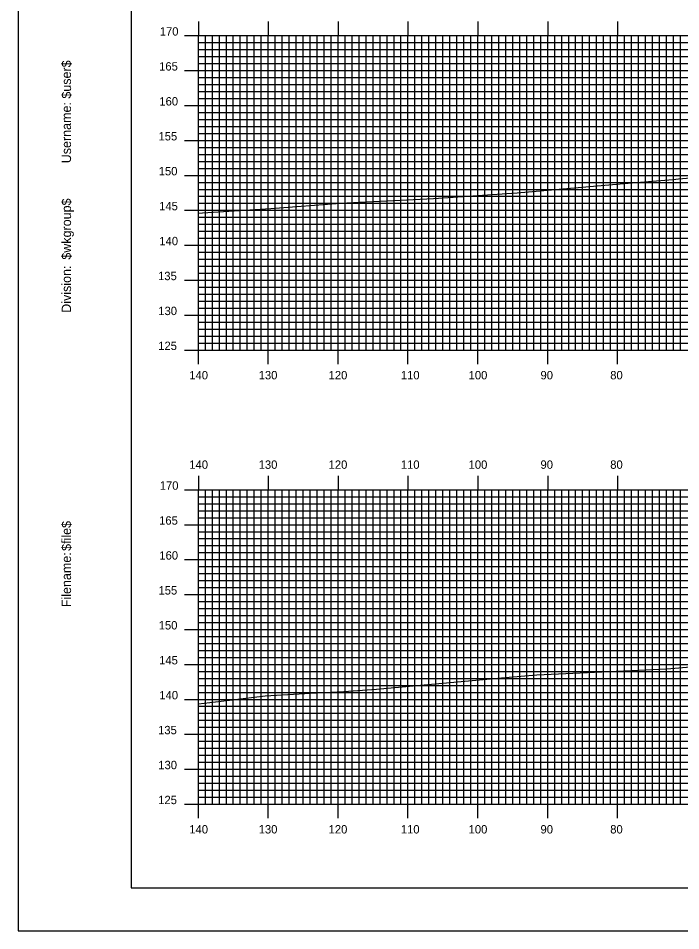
# Model space of a CAD drawing. Extents: x 1783041 to 1783384, y 442591 to 442811.
# Drawn here: x 1783040.7 to 1783135.5, y 442590.5 to 442721.2 of the extents above; entities that cross this region are included whole.
import ezdxf

# ---------------------------------------------------------------- set-up
doc = ezdxf.new("R2010")
doc.units = 0
for name, color, linetype in [('BORDER', 7, 'Continuous'), ('H_V ANNOTATION', 7, 'Continuous'), ('MAJOR', 7, 'Continuous'), ('MINOR', 7, 'Continuous'), ('PLOT BOUNDARY', 7, 'Continuous'), ('S_Roadway_Centerline', 7, 'Continuous')]:
    doc.layers.add(name, color=color, linetype=linetype)

msp = doc.modelspace()

# ---------------------------------------------------------------- linework, layer by layer
at = {"layer": 'BORDER'}
msp.add_lwpolyline([(1783056.86, 442596.67), (1783376.86, 442596.67), (1783376.86, 442806.67), (1783056.86, 442806.67)], close=True, dxfattribs=at)
at = {"layer": 'MAJOR'}
for p, q in [((1783066.46, 442720.67), (1783066.46, 442718.67)), ((1783076.46, 442720.67), (1783076.46, 442718.67)), ((1783086.46, 442720.67), (1783086.46, 442718.67)), ((1783096.46, 442720.67), (1783096.46, 442718.67)), ((1783106.46, 442720.67), (1783106.46, 442718.67)), ((1783116.46, 442720.67), (1783116.46, 442718.67)), ((1783126.46, 442720.67), (1783126.46, 442718.67)), ((1783064.46, 442718.67), (1783066.46, 442718.67)), ((1783066.46, 442718.67), (1783346.46, 442718.67)), ((1783066.46, 442673.67), (1783066.46, 442718.67)), ((1783066.46, 442673.67), (1783066.46, 442718.67)), ((1783066.46, 442718.67), (1783346.46, 442718.67)), ((1783076.46, 442673.67), (1783076.46, 442718.67)), ((1783086.46, 442673.67), (1783086.46, 442718.67)), ((1783096.46, 442673.67), (1783096.46, 442718.67)), ((1783106.46, 442673.67), (1783106.46, 442718.67)), ((1783116.46, 442673.67), (1783116.46, 442718.67)), ((1783126.46, 442673.67), (1783126.46, 442718.67)), ((1783064.46, 442713.67), (1783066.46, 442713.67)), ((1783066.46, 442713.67), (1783346.46, 442713.67)), ((1783064.46, 442708.67), (1783066.46, 442708.67)), ((1783066.46, 442708.67), (1783346.46, 442708.67)), ((1783064.46, 442703.67), (1783066.46, 442703.67)), ((1783066.46, 442703.67), (1783346.46, 442703.67)), ((1783064.46, 442698.67), (1783066.46, 442698.67)), ((1783066.46, 442698.67), (1783346.46, 442698.67)), ((1783064.46, 442693.67), (1783066.46, 442693.67)), ((1783066.46, 442693.67), (1783346.46, 442693.67)), ((1783064.46, 442688.67), (1783066.46, 442688.67)), ((1783066.46, 442688.67), (1783346.46, 442688.67)), ((1783064.46, 442683.67), (1783066.46, 442683.67)), ((1783066.46, 442683.67), (1783346.46, 442683.67)), ((1783064.46, 442678.67), (1783066.46, 442678.67)), ((1783066.46, 442678.67), (1783346.46, 442678.67)), ((1783064.46, 442673.67), (1783066.46, 442673.67)), ((1783066.46, 442673.67), (1783346.46, 442673.67)), ((1783066.46, 442673.67), (1783346.46, 442673.67)), ((1783066.46, 442671.66), (1783066.46, 442673.67)), ((1783076.46, 442671.66), (1783076.46, 442673.67)), ((1783086.46, 442671.66), (1783086.46, 442673.67)), ((1783096.46, 442671.66), (1783096.46, 442673.67)), ((1783106.46, 442671.66), (1783106.46, 442673.67)), ((1783116.46, 442671.66), (1783116.46, 442673.67)), ((1783126.46, 442671.66), (1783126.46, 442673.67)), ((1783066.46, 442655.67), (1783066.46, 442653.67)), ((1783076.46, 442655.67), (1783076.46, 442653.67)), ((1783086.46, 442655.67), (1783086.46, 442653.67)), ((1783096.46, 442655.67), (1783096.46, 442653.67)), ((1783106.46, 442655.67), (1783106.46, 442653.67)), ((1783116.46, 442655.67), (1783116.46, 442653.67)), ((1783126.46, 442655.67), (1783126.46, 442653.67)), ((1783064.46, 442653.67), (1783066.46, 442653.67)), ((1783066.46, 442653.67), (1783346.46, 442653.67)), ((1783066.46, 442608.67), (1783066.46, 442653.67)), ((1783066.46, 442608.67), (1783066.46, 442653.67)), ((1783066.46, 442653.67), (1783346.46, 442653.67)), ((1783076.46, 442608.67), (1783076.46, 442653.67)), ((1783086.46, 442608.67), (1783086.46, 442653.67)), ((1783096.46, 442608.67), (1783096.46, 442653.67)), ((1783106.46, 442608.67), (1783106.46, 442653.67)), ((1783116.46, 442608.67), (1783116.46, 442653.67)), ((1783126.46, 442608.67), (1783126.46, 442653.67)), ((1783064.46, 442648.67), (1783066.46, 442648.67)), ((1783066.46, 442648.67), (1783346.46, 442648.67)), ((1783064.46, 442643.67), (1783066.46, 442643.67)), ((1783066.46, 442643.67), (1783346.46, 442643.67)), ((1783064.46, 442638.67), (1783066.46, 442638.67)), ((1783066.46, 442638.67), (1783346.46, 442638.67)), ((1783064.46, 442633.67), (1783066.46, 442633.67)), ((1783066.46, 442633.67), (1783346.46, 442633.67)), ((1783064.46, 442628.67), (1783066.46, 442628.67)), ((1783066.46, 442628.67), (1783346.46, 442628.67)), ((1783064.46, 442623.67), (1783066.46, 442623.67)), ((1783066.46, 442623.67), (1783346.46, 442623.67)), ((1783064.46, 442618.67), (1783066.46, 442618.67)), ((1783066.46, 442618.67), (1783346.46, 442618.67)), ((1783064.46, 442613.67), (1783066.46, 442613.67)), ((1783066.46, 442613.67), (1783346.46, 442613.67)), ((1783064.46, 442608.67), (1783066.46, 442608.67)), ((1783066.46, 442608.67), (1783346.46, 442608.67)), ((1783066.46, 442608.67), (1783346.46, 442608.67)), ((1783066.46, 442606.66), (1783066.46, 442608.67)), ((1783076.46, 442606.66), (1783076.46, 442608.67)), ((1783086.46, 442606.66), (1783086.46, 442608.67)), ((1783096.46, 442606.66), (1783096.46, 442608.67)), ((1783106.46, 442606.66), (1783106.46, 442608.67)), ((1783116.46, 442606.66), (1783116.46, 442608.67)), ((1783126.46, 442606.66), (1783126.46, 442608.67))]:
    msp.add_line(p, q, dxfattribs=at)
at = {"layer": 'MINOR'}
for p, q in [((1783067.46, 442673.67), (1783067.46, 442718.67)), ((1783068.46, 442673.67), (1783068.46, 442718.67)), ((1783069.46, 442673.67), (1783069.46, 442718.67)), ((1783070.46, 442673.67), (1783070.46, 442718.67)), ((1783071.46, 442673.67), (1783071.46, 442718.67)), ((1783072.46, 442673.67), (1783072.46, 442718.67)), ((1783073.46, 442673.67), (1783073.46, 442718.67)), ((1783074.46, 442673.67), (1783074.46, 442718.67)), ((1783075.46, 442673.67), (1783075.46, 442718.67)), ((1783077.46, 442673.67), (1783077.46, 442718.67)), ((1783078.46, 442673.67), (1783078.46, 442718.67)), ((1783079.46, 442673.67), (1783079.46, 442718.67)), ((1783080.46, 442673.67), (1783080.46, 442718.67)), ((1783081.46, 442673.67), (1783081.46, 442718.67)), ((1783082.46, 442673.67), (1783082.46, 442718.67)), ((1783083.46, 442673.67), (1783083.46, 442718.67)), ((1783084.46, 442673.67), (1783084.46, 442718.67)), ((1783085.46, 442673.67), (1783085.46, 442718.67)), ((1783087.46, 442673.67), (1783087.46, 442718.67)), ((1783088.46, 442673.67), (1783088.46, 442718.67)), ((1783089.46, 442673.67), (1783089.46, 442718.67)), ((1783090.46, 442673.67), (1783090.46, 442718.67)), ((1783091.46, 442673.67), (1783091.46, 442718.67)), ((1783092.46, 442673.67), (1783092.46, 442718.67)), ((1783093.46, 442673.67), (1783093.46, 442718.67)), ((1783094.46, 442673.67), (1783094.46, 442718.67)), ((1783095.46, 442673.67), (1783095.46, 442718.67)), ((1783097.46, 442673.67), (1783097.46, 442718.67)), ((1783098.46, 442673.67), (1783098.46, 442718.67)), ((1783099.46, 442673.67), (1783099.46, 442718.67)), ((1783100.46, 442673.67), (1783100.46, 442718.67)), ((1783101.46, 442673.67), (1783101.46, 442718.67)), ((1783102.46, 442673.67), (1783102.46, 442718.67)), ((1783103.46, 442673.67), (1783103.46, 442718.67)), ((1783104.46, 442673.67), (1783104.46, 442718.67)), ((1783105.46, 442673.67), (1783105.46, 442718.67)), ((1783107.46, 442673.67), (1783107.46, 442718.67)), ((1783108.46, 442673.67), (1783108.46, 442718.67)), ((1783109.46, 442673.67), (1783109.46, 442718.67)), ((1783110.46, 442673.67), (1783110.46, 442718.67)), ((1783111.46, 442673.67), (1783111.46, 442718.67)), ((1783112.46, 442673.67), (1783112.46, 442718.67)), ((1783113.46, 442673.67), (1783113.46, 442718.67)), ((1783114.46, 442673.67), (1783114.46, 442718.67)), ((1783115.46, 442673.67), (1783115.46, 442718.67)), ((1783117.46, 442673.67), (1783117.46, 442718.67)), ((1783118.46, 442673.67), (1783118.46, 442718.67)), ((1783119.46, 442673.67), (1783119.46, 442718.67)), ((1783120.46, 442673.67), (1783120.46, 442718.67)), ((1783121.46, 442673.67), (1783121.46, 442718.67)), ((1783122.46, 442673.67), (1783122.46, 442718.67)), ((1783123.46, 442673.67), (1783123.46, 442718.67)), ((1783124.46, 442673.67), (1783124.46, 442718.67)), ((1783125.46, 442673.67), (1783125.46, 442718.67)), ((1783127.46, 442673.67), (1783127.46, 442718.67)), ((1783128.46, 442673.67), (1783128.46, 442718.67)), ((1783129.46, 442673.67), (1783129.46, 442718.67)), ((1783130.46, 442673.67), (1783130.46, 442718.67)), ((1783131.46, 442673.67), (1783131.46, 442718.67)), ((1783132.46, 442673.67), (1783132.46, 442718.67)), ((1783133.46, 442673.67), (1783133.46, 442718.67)), ((1783134.46, 442673.67), (1783134.46, 442718.67)), ((1783135.46, 442673.67), (1783135.46, 442718.67)), ((1783066.46, 442717.67), (1783346.46, 442717.67)), ((1783066.46, 442717.67), (1783068.46, 442717.67)), ((1783066.46, 442716.67), (1783346.46, 442716.67)), ((1783066.46, 442716.67), (1783068.46, 442716.67)), ((1783066.46, 442715.67), (1783346.46, 442715.67)), ((1783066.46, 442715.67), (1783068.46, 442715.67)), ((1783066.46, 442714.67), (1783346.46, 442714.67)), ((1783066.46, 442714.67), (1783068.46, 442714.67)), ((1783066.46, 442712.67), (1783346.46, 442712.67)), ((1783066.46, 442712.67), (1783068.46, 442712.67)), ((1783066.46, 442711.67), (1783346.46, 442711.67)), ((1783066.46, 442711.67), (1783068.46, 442711.67)), ((1783066.46, 442710.67), (1783346.46, 442710.67)), ((1783066.46, 442710.67), (1783068.46, 442710.67)), ((1783066.46, 442709.67), (1783346.46, 442709.67)), ((1783066.46, 442709.67), (1783068.46, 442709.67)), ((1783066.46, 442707.67), (1783346.46, 442707.67)), ((1783066.46, 442707.67), (1783068.46, 442707.67)), ((1783066.46, 442706.67), (1783346.46, 442706.67)), ((1783066.46, 442706.67), (1783068.46, 442706.67)), ((1783066.46, 442705.67), (1783346.46, 442705.67)), ((1783066.46, 442705.67), (1783068.46, 442705.67)), ((1783066.46, 442704.67), (1783346.46, 442704.67)), ((1783066.46, 442704.67), (1783068.46, 442704.67)), ((1783066.46, 442702.67), (1783346.46, 442702.67)), ((1783066.46, 442702.67), (1783068.46, 442702.67)), ((1783066.46, 442701.67), (1783346.46, 442701.67)), ((1783066.46, 442701.67), (1783068.46, 442701.67)), ((1783066.46, 442700.67), (1783346.46, 442700.67)), ((1783066.46, 442700.67), (1783068.46, 442700.67)), ((1783066.46, 442699.67), (1783346.46, 442699.67)), ((1783066.46, 442699.67), (1783068.46, 442699.67)), ((1783066.46, 442697.67), (1783346.46, 442697.67)), ((1783066.46, 442697.67), (1783068.46, 442697.67)), ((1783066.46, 442696.67), (1783346.46, 442696.67)), ((1783066.46, 442696.67), (1783068.46, 442696.67)), ((1783066.46, 442695.67), (1783346.46, 442695.67)), ((1783066.46, 442695.67), (1783068.46, 442695.67)), ((1783066.46, 442694.67), (1783346.46, 442694.67)), ((1783066.46, 442694.67), (1783068.46, 442694.67)), ((1783066.46, 442692.67), (1783346.46, 442692.67)), ((1783066.46, 442692.67), (1783068.46, 442692.67)), ((1783066.46, 442691.67), (1783346.46, 442691.67)), ((1783066.46, 442691.67), (1783068.46, 442691.67)), ((1783066.46, 442690.67), (1783346.46, 442690.67)), ((1783066.46, 442690.67), (1783068.46, 442690.67)), ((1783066.46, 442689.67), (1783346.46, 442689.67)), ((1783066.46, 442689.67), (1783068.46, 442689.67)), ((1783066.46, 442687.67), (1783346.46, 442687.67)), ((1783066.46, 442687.67), (1783068.46, 442687.67)), ((1783066.46, 442686.67), (1783346.46, 442686.67)), ((1783066.46, 442686.67), (1783068.46, 442686.67)), ((1783066.46, 442685.67), (1783346.46, 442685.67)), ((1783066.46, 442685.67), (1783068.46, 442685.67)), ((1783066.46, 442684.67), (1783346.46, 442684.67)), ((1783066.46, 442684.67), (1783068.46, 442684.67)), ((1783066.46, 442682.67), (1783346.46, 442682.67)), ((1783066.46, 442682.67), (1783068.46, 442682.67)), ((1783066.46, 442681.67), (1783346.46, 442681.67)), ((1783066.46, 442681.67), (1783068.46, 442681.67)), ((1783066.46, 442680.67), (1783346.46, 442680.67)), ((1783066.46, 442680.67), (1783068.46, 442680.67)), ((1783066.46, 442679.67), (1783346.46, 442679.67)), ((1783066.46, 442679.67), (1783068.46, 442679.67)), ((1783066.46, 442677.67), (1783346.46, 442677.67)), ((1783066.46, 442677.67), (1783068.46, 442677.67)), ((1783066.46, 442676.67), (1783346.46, 442676.67)), ((1783066.46, 442676.67), (1783068.46, 442676.67)), ((1783066.46, 442675.67), (1783346.46, 442675.67)), ((1783066.46, 442675.67), (1783068.46, 442675.67)), ((1783066.46, 442674.67), (1783346.46, 442674.67)), ((1783066.46, 442674.67), (1783068.46, 442674.67)), ((1783066.46, 442652.67), (1783346.46, 442652.67)), ((1783066.46, 442652.67), (1783068.46, 442652.67)), ((1783067.46, 442608.67), (1783067.46, 442653.67)), ((1783068.46, 442608.67), (1783068.46, 442653.67)), ((1783069.46, 442608.67), (1783069.46, 442653.67)), ((1783070.46, 442608.67), (1783070.46, 442653.67)), ((1783071.46, 442608.67), (1783071.46, 442653.67)), ((1783072.46, 442608.67), (1783072.46, 442653.67)), ((1783073.46, 442608.67), (1783073.46, 442653.67)), ((1783074.46, 442608.67), (1783074.46, 442653.67)), ((1783075.46, 442608.67), (1783075.46, 442653.67)), ((1783077.46, 442608.67), (1783077.46, 442653.67)), ((1783078.46, 442608.67), (1783078.46, 442653.67)), ((1783079.46, 442608.67), (1783079.46, 442653.67)), ((1783080.46, 442608.67), (1783080.46, 442653.67)), ((1783081.46, 442608.67), (1783081.46, 442653.67)), ((1783082.46, 442608.67), (1783082.46, 442653.67)), ((1783083.46, 442608.67), (1783083.46, 442653.67)), ((1783084.46, 442608.67), (1783084.46, 442653.67)), ((1783085.46, 442608.67), (1783085.46, 442653.67)), ((1783087.46, 442608.67), (1783087.46, 442653.67)), ((1783088.46, 442608.67), (1783088.46, 442653.67)), ((1783089.46, 442608.67), (1783089.46, 442653.67)), ((1783090.46, 442608.67), (1783090.46, 442653.67)), ((1783091.46, 442608.67), (1783091.46, 442653.67)), ((1783092.46, 442608.67), (1783092.46, 442653.67)), ((1783093.46, 442608.67), (1783093.46, 442653.67)), ((1783094.46, 442608.67), (1783094.46, 442653.67)), ((1783095.46, 442608.67), (1783095.46, 442653.67)), ((1783097.46, 442608.67), (1783097.46, 442653.67)), ((1783098.46, 442608.67), (1783098.46, 442653.67)), ((1783099.46, 442608.67), (1783099.46, 442653.67)), ((1783100.46, 442608.67), (1783100.46, 442653.67)), ((1783101.46, 442608.67), (1783101.46, 442653.67)), ((1783102.46, 442608.67), (1783102.46, 442653.67)), ((1783103.46, 442608.67), (1783103.46, 442653.67)), ((1783104.46, 442608.67), (1783104.46, 442653.67)), ((1783105.46, 442608.67), (1783105.46, 442653.67)), ((1783107.46, 442608.67), (1783107.46, 442653.67)), ((1783108.46, 442608.67), (1783108.46, 442653.67)), ((1783109.46, 442608.67), (1783109.46, 442653.67)), ((1783110.46, 442608.67), (1783110.46, 442653.67)), ((1783111.46, 442608.67), (1783111.46, 442653.67)), ((1783112.46, 442608.67), (1783112.46, 442653.67)), ((1783113.46, 442608.67), (1783113.46, 442653.67)), ((1783114.46, 442608.67), (1783114.46, 442653.67)), ((1783115.46, 442608.67), (1783115.46, 442653.67)), ((1783117.46, 442608.67), (1783117.46, 442653.67)), ((1783118.46, 442608.67), (1783118.46, 442653.67)), ((1783119.46, 442608.67), (1783119.46, 442653.67)), ((1783120.46, 442608.67), (1783120.46, 442653.67)), ((1783121.46, 442608.67), (1783121.46, 442653.67)), ((1783122.46, 442608.67), (1783122.46, 442653.67)), ((1783123.46, 442608.67), (1783123.46, 442653.67)), ((1783124.46, 442608.67), (1783124.46, 442653.67)), ((1783125.46, 442608.67), (1783125.46, 442653.67)), ((1783127.46, 442608.67), (1783127.46, 442653.67)), ((1783128.46, 442608.67), (1783128.46, 442653.67)), ((1783129.46, 442608.67), (1783129.46, 442653.67)), ((1783130.46, 442608.67), (1783130.46, 442653.67)), ((1783131.46, 442608.67), (1783131.46, 442653.67)), ((1783132.46, 442608.67), (1783132.46, 442653.67)), ((1783133.46, 442608.67), (1783133.46, 442653.67)), ((1783134.46, 442608.67), (1783134.46, 442653.67)), ((1783135.46, 442608.67), (1783135.46, 442653.67)), ((1783066.46, 442651.67), (1783346.46, 442651.67)), ((1783066.46, 442651.67), (1783068.46, 442651.67)), ((1783066.46, 442650.67), (1783346.46, 442650.67)), ((1783066.46, 442650.67), (1783068.46, 442650.67)), ((1783066.46, 442649.67), (1783346.46, 442649.67)), ((1783066.46, 442649.67), (1783068.46, 442649.67)), ((1783066.46, 442647.67), (1783346.46, 442647.67)), ((1783066.46, 442647.67), (1783068.46, 442647.67)), ((1783066.46, 442646.67), (1783346.46, 442646.67)), ((1783066.46, 442646.67), (1783068.46, 442646.67)), ((1783066.46, 442645.67), (1783346.46, 442645.67)), ((1783066.46, 442645.67), (1783068.46, 442645.67)), ((1783066.46, 442644.67), (1783346.46, 442644.67)), ((1783066.46, 442644.67), (1783068.46, 442644.67)), ((1783066.46, 442642.67), (1783346.46, 442642.67)), ((1783066.46, 442642.67), (1783068.46, 442642.67)), ((1783066.46, 442641.67), (1783346.46, 442641.67)), ((1783066.46, 442641.67), (1783068.46, 442641.67)), ((1783066.46, 442640.67), (1783346.46, 442640.67)), ((1783066.46, 442640.67), (1783068.46, 442640.67)), ((1783066.46, 442639.67), (1783346.46, 442639.67)), ((1783066.46, 442639.67), (1783068.46, 442639.67)), ((1783066.46, 442637.67), (1783346.46, 442637.67)), ((1783066.46, 442637.67), (1783068.46, 442637.67)), ((1783066.46, 442636.67), (1783346.46, 442636.67)), ((1783066.46, 442636.67), (1783068.46, 442636.67)), ((1783066.46, 442635.67), (1783346.46, 442635.67)), ((1783066.46, 442635.67), (1783068.46, 442635.67)), ((1783066.46, 442634.67), (1783346.46, 442634.67)), ((1783066.46, 442634.67), (1783068.46, 442634.67)), ((1783066.46, 442632.67), (1783346.46, 442632.67)), ((1783066.46, 442632.67), (1783068.46, 442632.67)), ((1783066.46, 442631.67), (1783346.46, 442631.67)), ((1783066.46, 442631.67), (1783068.46, 442631.67)), ((1783066.46, 442630.67), (1783346.46, 442630.67)), ((1783066.46, 442630.67), (1783068.46, 442630.67)), ((1783066.46, 442629.67), (1783346.46, 442629.67)), ((1783066.46, 442629.67), (1783068.46, 442629.67)), ((1783066.46, 442627.67), (1783346.46, 442627.67)), ((1783066.46, 442627.67), (1783068.46, 442627.67)), ((1783066.46, 442626.67), (1783346.46, 442626.67)), ((1783066.46, 442626.67), (1783068.46, 442626.67)), ((1783066.46, 442625.67), (1783346.46, 442625.67)), ((1783066.46, 442625.67), (1783068.46, 442625.67)), ((1783066.46, 442624.67), (1783346.46, 442624.67)), ((1783066.46, 442624.67), (1783068.46, 442624.67)), ((1783066.46, 442622.67), (1783346.46, 442622.67)), ((1783066.46, 442622.67), (1783068.46, 442622.67)), ((1783066.46, 442621.67), (1783346.46, 442621.67)), ((1783066.46, 442621.67), (1783068.46, 442621.67)), ((1783066.46, 442620.67), (1783346.46, 442620.67)), ((1783066.46, 442620.67), (1783068.46, 442620.67)), ((1783066.46, 442619.67), (1783346.46, 442619.67)), ((1783066.46, 442619.67), (1783068.46, 442619.67)), ((1783066.46, 442617.67), (1783346.46, 442617.67)), ((1783066.46, 442617.67), (1783068.46, 442617.67)), ((1783066.46, 442616.67), (1783346.46, 442616.67)), ((1783066.46, 442616.67), (1783068.46, 442616.67)), ((1783066.46, 442615.67), (1783346.46, 442615.67)), ((1783066.46, 442615.67), (1783068.46, 442615.67)), ((1783066.46, 442614.67), (1783346.46, 442614.67)), ((1783066.46, 442614.67), (1783068.46, 442614.67)), ((1783066.46, 442612.67), (1783346.46, 442612.67)), ((1783066.46, 442612.67), (1783068.46, 442612.67)), ((1783066.46, 442611.67), (1783346.46, 442611.67)), ((1783066.46, 442611.67), (1783068.46, 442611.67)), ((1783066.46, 442610.67), (1783346.46, 442610.67)), ((1783066.46, 442610.67), (1783068.46, 442610.67)), ((1783066.46, 442609.67), (1783346.46, 442609.67)), ((1783066.46, 442609.67), (1783068.46, 442609.67))]:
    msp.add_line(p, q, dxfattribs=at)
at = {"layer": 'PLOT BOUNDARY'}
msp.add_lwpolyline([(1783040.67, 442590.55), (1783380.67, 442590.55), (1783380.67, 442810.55), (1783040.67, 442810.55)], close=True, dxfattribs=at)
at = {"layer": 'S_Roadway_Centerline'}
for points in [[(1783066.46, 442693.28), (1783067.03, 442693.33), (1783076.81, 442693.91), (1783086.78, 442694.67), (1783089.56, 442694.83), (1783100.13, 442695.35), (1783111.33, 442696.12), (1783112.07, 442696.16), (1783126.85, 442697.44), (1783134.36, 442698.09), (1783134.78, 442698.12), (1783135.18, 442698.17), (1783149.65, 442699.39)], [(1783066.46, 442623.05), (1783069.71, 442623.42), (1783076, 442624.18), (1783082.49, 442624.55), (1783087.28, 442624.78), (1783091.97, 442625.13), (1783110.35, 442626.8), (1783114.89, 442627.2), (1783133.49, 442628.06), (1783137.46, 442628.35), (1783145.58, 442629.31), (1783154.56, 442630.31), (1783160.6, 442631.03), (1783177.46, 442632.36), (1783180.18, 442632.54), (1783182.69, 442632.67), (1783196.75, 442633.66), (1783205.53, 442634.29), (1783215.14, 442634.91), (1783223.28, 442635.36), (1783226.96, 442635.7), (1783247.96, 442637.22)]]:
    msp.add_lwpolyline(points, dxfattribs=at)

# ---------------------------------------------------------------- texts
at = {"layer": 'BORDER'}
for s, p in [('$user$', (1783048.23, 442709.65)), ('$user$', (1783048.23, 442709.65)), ('Username:', (1783048.23, 442700.4)), ('Username:', (1783048.23, 442700.4)), ('$wkgroup$', (1783048.23, 442686.6)), ('$wkgroup$', (1783048.23, 442686.6)), ('Division:', (1783048.23, 442679)), ('Division:', (1783048.23, 442679)), ('$file$', (1783048.23, 442644.92)), ('$file$', (1783048.23, 442644.92)), ('Filename:', (1783048.23, 442636.86)), ('Filename:', (1783048.23, 442636.86))]:
    msp.add_text(s, height=1.339, rotation=90, dxfattribs=at).set_placement(p)
at = {"layer": 'H_V ANNOTATION'}
for s, p in [('170', (1783060.93, 442718.67)), ('165', (1783060.84, 442713.67)), ('160', (1783060.87, 442708.67)), ('155', (1783060.75, 442703.67)), ('150', (1783060.78, 442698.67)), ('145', (1783060.84, 442693.67)), ('140', (1783060.87, 442688.67)), ('135', (1783060.69, 442683.67)), ('130', (1783060.72, 442678.67)), ('125', (1783060.71, 442673.67)), ('140', (1783065.16, 442669.47)), ('130', (1783075.09, 442669.47)), ('120', (1783085.1, 442669.47)), ('110', (1783095.44, 442669.47)), ('100', (1783105.14, 442669.47)), ('90', (1783115.43, 442669.47)), ('80', (1783125.41, 442669.47)), ('140', (1783065.16, 442656.67)), ('130', (1783075.09, 442656.67)), ('120', (1783085.1, 442656.67)), ('110', (1783095.44, 442656.67)), ('100', (1783105.14, 442656.67)), ('90', (1783115.43, 442656.67)), ('80', (1783125.41, 442656.67)), ('170', (1783060.93, 442653.67)), ('165', (1783060.84, 442648.67)), ('160', (1783060.87, 442643.67)), ('155', (1783060.75, 442638.67)), ('150', (1783060.78, 442633.67)), ('145', (1783060.84, 442628.67)), ('140', (1783060.87, 442623.67)), ('135', (1783060.69, 442618.67)), ('130', (1783060.72, 442613.67)), ('125', (1783060.71, 442608.67)), ('140', (1783065.16, 442604.47)), ('130', (1783075.09, 442604.47)), ('120', (1783085.1, 442604.47)), ('110', (1783095.44, 442604.47)), ('100', (1783105.14, 442604.47)), ('90', (1783115.43, 442604.47)), ('80', (1783125.41, 442604.47))]:
    msp.add_text(s, height=1.2, dxfattribs=at).set_placement(p)
at = {"layer": 'MAJOR'}
for p in [(1783066.45, 442673.67), (1783066.45, 442608.67)]:
    msp.add_text('-', height=0.012, dxfattribs=at).set_placement(p)

doc.saveas('drawing.dxf')
